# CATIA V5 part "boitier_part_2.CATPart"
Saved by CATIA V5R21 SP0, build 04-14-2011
Part number: boitier_part_2
Bounding box of the stored display mesh (mm): x 133.487 to 168.487, y -93.149 to -33.149, z 0 to 3.6
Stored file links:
  C:\Users\zerma\Pictures\CAO\boitier_part_2.CATPart
  C:\Users\zerma\Pictures\CAO\Boitier batterie 5V.CATProduct
  C:\Users\zerma\Pictures\CAO\boitier_part_1.CATPart
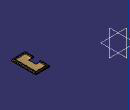
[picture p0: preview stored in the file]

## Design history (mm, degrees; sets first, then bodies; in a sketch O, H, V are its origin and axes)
Set1
  DatumCurve1 to DatumCurve7: linked copy from another document
Body1 (main body)
  Sketch1 on xy-plane, origin (0, 0, 0), H (1, 0, 0), V (0, 1, 0)
    line L1 (168.4869, -33.1493) -> (168.4869, -93.1493)
    line L2 (168.4869, -93.1493) -> (133.4869, -93.1493)
    line L3 (133.4869, -93.1493) -> (133.4869, -33.1493)
    line L4 (133.4869, -33.1493) -> (168.4869, -33.1493)
    reference projected line E1 (133.4869, -93.1493) -> (133.4869, -35.1493) from edge of DatumCurve5
    reference projected line E2 (133.4869, -93.1493) -> (133.9869, -93.1493) from edge of DatumCurve7
    length L1 = 60
    length L4 = 35
    vertical: L1 V, L3 V
    horizontal: L2 H, L4 H
    coincidence: L3 E1, L2 E2
  Pad1: profile Sketch1, direction (0, 0, 1), length 1
  Sketch2 on end face of Pad1, origin (0, 0, 1), H (1, 0, 0), V (0, 1, 0)
    line L1 (166.2369, -91.3993) -> (135.7369, -91.3993)
    line L2 (135.7369, -91.3993) -> (135.7369, -34.8993)
    line L3 (135.7369, -34.8993) -> (166.2369, -34.8993)
    line L4 (166.2369, -34.8993) -> (166.2369, -91.3993)
    reference projected line E1 (133.4869, -33.1493) -> (133.4869, -93.1493) from edge [face of Pad1 from Sketch1.L3 | end face of Pad1]
    reference projected line E2 (133.4869, -93.1493) -> (168.4869, -93.1493) from edge [start face of Pad1 | face of Pad1 from Sketch1.L2]
    line L5 (137.7369, -36.8993) -> (164.2369, -36.8993)
    line L6 (164.2369, -36.8993) -> (164.2369, -89.3993)
    line L7 (164.2369, -89.3993) -> (137.7369, -89.3993)
    line L8 (137.7369, -89.3993) -> (137.7369, -36.8993)
    distance L2 E1 = 2.25
    distance L1 E2 = 1.75
    distance L6 L4 = 2
    distance L5 L3 = 2
    distance L8 L2 = 2
    distance L7 L1 = 2
    length L2 = 56.5
    length L1 = 30.5
    horizontal: L1 H, L3 H, L5 H, L7 H
    vertical: L2 V, L4 V, L6 V, L8 V
  Pad2: profile Sketch2, direction (0, 0, 1), length 2.6
  Sketch3 on end face of Pad1, origin (0, 0, 1), H (1, 0, 0), V (0, 1, 0)
    line L1 (133.4869, -54.3993) -> (146.4869, -54.3993)
    line L2 (146.4869, -54.3993) -> (146.4869, -72.3993)
    line L3 (146.4869, -72.3993) -> (133.4869, -72.3993)
    line L4 (133.4869, -72.3993) -> (133.4869, -54.3993)
    reference projected line E1 (136.4869, -89.3993) -> (162.9869, -89.3993) from edge [end face of Pad2 | face of Pad2 from Sketch2.L7]
    reference projected line E2 (133.4869, -33.1493) -> (133.4869, -93.1493) from edge [face of Pad1 from Sketch1.L3 | end face of Pad1]
    length L2 = 18
    length L1 = 13
    distance L3 E1 = 17
    distance L4 E2 = 0
    horizontal: L1 H, L3 H
    vertical: L2 V, L4 V
  Pocket1: profile Sketch3, direction (0, 0, -1), length 5, mirrored extent
  CLDGeom1 "Maillage.1"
